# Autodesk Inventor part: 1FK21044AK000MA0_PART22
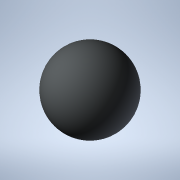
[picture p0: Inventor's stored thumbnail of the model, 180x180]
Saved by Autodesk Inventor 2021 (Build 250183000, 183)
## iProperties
Created: 2025-04
Part Number: 1FK21044AK000MA0_PART22
Material: Generic
Catalog Web Link: www.3dfindit.com
Description: -Servo synchronous motor
Document SubType Name: Modeling
Designer: psAdmin
Mass: 0.137258 g
Surface Area: 1.2868 cm^2
Volume: 0.137258 cm^3
Density: 1 g/cm^3
Appearance: PSOLRGB-212-217-219
Category: PARTsolutions
Title: 1FK21044AK000MA0_PART22
Author: Cadenas PARTsolutions
Comments: Servo synchronous motor
Sending System: PARTsolutions
Preprocessor: ST-DEVELOPER v19.3
PSOL_IDENT_0: {$CADENAS_DATA/23d-libs/siemens_ag/_cat_/87/f4/1fk21044ak000ma0.prj},216 {VTYP=3D},{NB=1FK21044AK000
PSOL_IDENT_1: MA0_PART22},{LINA=1FK21044AK000MA0_PART22},{NN=1FK21044AK000MA0_PART22},{NOPRJ=TRUE},{DATE=19.08.202
PSOL_IDENT_2: 5 14:00:48},{GEOMDATE=30.07.2025 02:00:50},{VERSION=},{LINEID=10},{WBVAR=},{WBNUMERIC=}  {NB=1FK2104
PSOL_IDENT_3: 4AK000MA0_PART22},{LINA=1FK21044AK000MA0_PART22},{KT=DUMMY},{PREVIEW=../../../_pool_/cb/72/p_d211_xx
PSOL_IDENT_4: _00434j.png},{DESCSHORT=SIMOTICS S-1FK2 HD, SINAMICS S210 3AC 400V-480V, 0.95 Nm, 6000 rpm},{DESCLON
PSOL_IDENT_5: G=SIMOTICS S-1FK2 HD servo motor M0=1.27 Nm; PN = 0.6 kW at nN=6000 rpm (380-480 V); PN = 0.4 kW at
PSOL_IDENT_6: nN=3000 rpm (200-240 V); degree of protection IP64; cylindrical shaft D19x40mm; absolute encoder 22-
PSOL_IDENT_7: bit + 12-bit multiturn (encoder AM22DQC); with OCC interface; plug size M17, rotatable; SIMOTICS S-1
PSOL_IDENT_8: FK2 servomotorfor a wide range of uses in industrial environments. SIMOTICS S‑1FK2 servomotors are c
PSOL_IDENT_9: ompact synchronous motors with a high dynamic performance that set themselves apart as a result of t
PSOL_IDENT_10: heir high power density, degree of protection and overload capability. The motors are available in t
PSOL_IDENT_11: wo variants: as High Dynamic variant (highest dynamic performance as a result of the low intrinsic m
PSOL_IDENT_12: oment of inertia for applications demanding a high dynamic performance with low moved masses) - and
PSOL_IDENT_13: as Compact variant (precise and stable closed-loop control for medium up to large moved masses as a
PSOL_IDENT_14: result of a medium intrinsic moment of inertia). SIMOTICSS‑1FK2 servomotors fully exploit their stre
PSOL_IDENT_15: ngths in a system with the SINAMICSS210 frequency converter and simple connection using the one cabl
PSOL_IDENT_16: e connection (OCC). Advantages include the short control and positioning times, fast and precise cor
PSOL_IDENT_17: rection of disturbing quantities as well as stable control with a high dynamic performance. The serv
PSOL_IDENT_18: o motors can be configured to address a wide range of requirements. For example with and without hol
PSOL_IDENT_19: ding brake, IP64 or IP65 degree of protection, singleturn or multiturn absolute encoders - to name j
PSOL_IDENT_20: ust a few. Further, the servomotors are available in different shaft heights extending from 20 to 10
PSOL_IDENT_21: 0. A shaft sealing ring is available to achieve an IP65 degree of protection and for subsequent moun
PSOL_IDENT_22: ting at the motor or as spare part. SIMOTICS - the optimum motor for each and every motion control a
PSOL_IDENT_23: pplication.},{INTNO=195125056312},{SUPPLIERALTNO=1FK2104-4AK00-0MA0},{MANUID=1FK21044AK000MA0},{MANU
PSOL_IDENT_24: NAME=Siemens},{MANUTYPEDESC=Synchronous motor 1FK2-HD 1,27 Nm},{AAU732=SIMOTICS},{AAO057=S-1FK2},{AA
PSOL_IDENT_25: U734=SIMOTICS S-1FK2 HD servo motor M0=1.27 Nm; PN = 0.6 kW at nN=6000 rpm (380-480 V); PN = 0.4 kW
PSOL_IDENT_26: at nN=3000 rpm (200-240 V); degree of protection IP64; cylindrical shaft D19x40mm; absolute encoder
PSOL_IDENT_27: 22-bit + 12-bit multiturn (encoder AM22DQC); with OCC interface; plug size M17, rotatable;},{AAW338=
PSOL_IDENT_28: Synchronous motor 1FK2-HD 1,27 Nm},{AAO742=SIMOTICS},{AAO663=4042948690994},{NOCUPEROU=1},{PRICEQUAN
PSOL_IDENT_29: TITY=1},{QUANTITYMIN=1},{QUANTITYINT=1},{CTN=85015100},{COO=DE},{AAO676=1FK2104-4AK00-0MA0},{AAO677=
PSOL_IDENT_30: Siemens AG},{ORDERUNIT=C62},{CONTENTUNIT=C62}
NB: 1FK21044AK000MA0_PART22
NT: Servo synchronous motor
NBSYN: $MANUID._PART22
LINA: 1FK21044AK000MA0_PART22
CATALOG: SIEMENS
PREVIEW: ../../../_pool_/cb/72/p_d211_xx_00434j.png
DESCSHORT: SIMOTICS S-1FK2 HD, SINAMICS S210 3AC 400V-480V, 0.95 Nm, 6000 rpm
DESCLONG: SIMOTICS S-1FK2 HD servo motor M0=1.27 Nm; PN = 0.6 kW at nN=6000 rpm (380-480 V); PN = 0.4 kW at nN=3000 rpm (200-240 V); degree of protection IP64; cylindrica
INTNO: 195125056312
SUPPLIERALTNO: 1FK2104-4AK00-0MA0
MANUID: 1FK21044AK000MA0
MANUNAME: Siemens
MANUTYPEDESC: Synchronous motor 1FK2-HD 1,27 Nm
AAU732: SIMOTICS
AAO057: S-1FK2
AAU734: SIMOTICS S-1FK2 HD servo motor M0=1.27 Nm; PN = 0.6 kW at nN=6000 rpm (380-480 V); PN = 0.4 kW at nN=3000 rpm (200-240 V); degree of protection IP64; cylindrica
AAW338: Synchronous motor 1FK2-HD 1,27 Nm
AAO742: SIMOTICS
AAO663: 4042948690994.0
NOCUPEROU: 1
PRICEQUANTITY: 1
QUANTITYMIN: 1
QUANTITYINT: 1
CTN: 85015100
COO: DE
ARTICLENO: 1FK21044AK000MA0_PART22
BOMINFO: 1FK21044AK000MA0_PART22
CREATOR: CADENAS GmbH
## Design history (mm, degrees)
feature "2025_04_17_15_37_40_0588"
body "Solid1"
